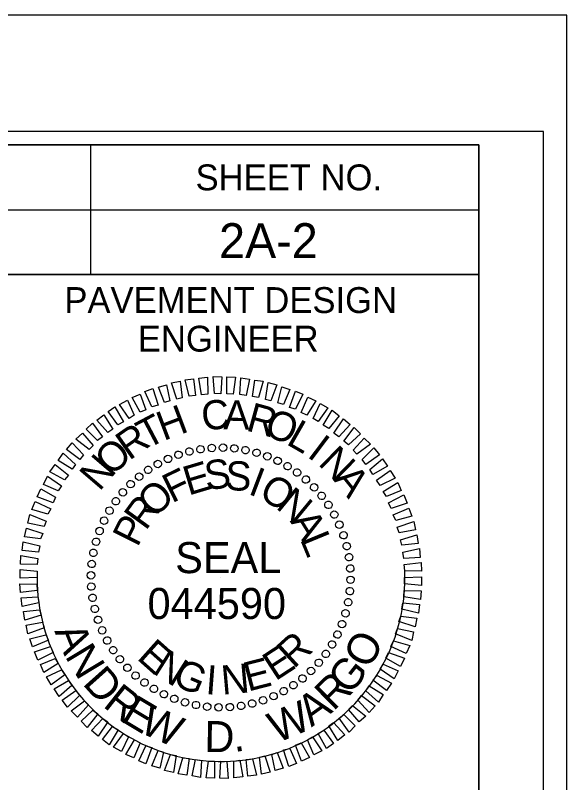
# Model space of a CAD drawing. Extents: x 3025871 to 3026431, y 707165 to 707825.
# Drawn here: x 3026258.64 to 3026274.62, y 707539.82 to 707562.05 of the extents above; entities that cross this region are included whole.
import ezdxf

# ---------------------------------------------------------------- set-up
doc = ezdxf.new("R2010")
doc.units = 0
for name, color, linetype in [('Old_Level_39', 7, 'Continuous'), ('Prop DSN Text', 7, 'Continuous'), ('Sheet Block Title CELL', 7, 'Continuous'), ('Sheet Cutting Line CELL', 7, 'Continuous'), ('Sheet Sticker Exception Certification CELL', 7, 'Continuous'), ('Typical Terminator CELL', 7, 'Continuous')]:
    doc.layers.add(name, color=color, linetype=linetype)

msp = doc.modelspace()

# ---------------------------------------------------------------- linework, layer by layer
at = {"layer": 'Old_Level_39'}
msp.add_lwpolyline([(3026273.948, 707558.686), (3026023.973, 707558.686), (3026023.973, 707400.421), (3026273.948, 707400.421)], close=True, dxfattribs=at)
at = {"layer": 'Prop DSN Text'}
msp.add_arc((3026264.604, 707545.767), 5.331, 180.0118, 2.0847, dxfattribs=at)
at = {"layer": 'Sheet Block Title CELL'}
for p, q in [((3026263.683, 707549.418), (3026263.683, 707549.418)), ((3026264.013, 707549.478), (3026264.013, 707549.478)), ((3026264.336, 707549.523), (3026264.336, 707549.523)), ((3026264.666, 707549.531), (3026264.666, 707549.531)), ((3026264.996, 707549.508), (3026264.996, 707549.508)), ((3026265.318, 707549.456), (3026265.318, 707549.456)), ((3026265.633, 707549.388), (3026265.633, 707549.388)), ((3026263.068, 707549.208), (3026263.068, 707549.208)), ((3026263.368, 707549.328), (3026263.368, 707549.328)), ((3026265.948, 707549.283), (3026265.948, 707549.283)), ((3026266.248, 707549.148), (3026266.248, 707549.148)), ((3026262.776, 707549.058), (3026262.776, 707549.058)), ((3026266.541, 707548.998), (3026266.541, 707548.998)), ((3026262.228, 707548.698), (3026262.228, 707548.698)), ((3026262.491, 707548.886), (3026262.491, 707548.886)), ((3026266.811, 707548.811), (3026266.811, 707548.811)), ((3026261.981, 707548.473), (3026261.981, 707548.473)), ((3026267.073, 707548.608), (3026267.073, 707548.608)), ((3026267.306, 707548.383), (3026267.306, 707548.383)), ((3026261.756, 707548.241), (3026261.756, 707548.241)), ((3026267.531, 707548.136), (3026267.531, 707548.136)), ((3026261.553, 707547.978), (3026261.553, 707547.978)), ((3026267.718, 707547.873), (3026267.718, 707547.873)), ((3026261.366, 707547.708), (3026261.366, 707547.708)), ((3026267.891, 707547.588), (3026267.891, 707547.588)), ((3026261.216, 707547.416), (3026261.216, 707547.416)), ((3026268.041, 707547.296), (3026268.041, 707547.296)), ((3026261.081, 707547.116), (3026261.081, 707547.116)), ((3026268.161, 707546.996), (3026268.161, 707546.996)), ((3026260.976, 707546.801), (3026260.976, 707546.801)), ((3026260.908, 707546.486), (3026260.908, 707546.486)), ((3026268.251, 707546.681), (3026268.251, 707546.681)), ((3026268.311, 707546.351), (3026268.311, 707546.351)), ((3026260.856, 707546.163), (3026260.856, 707546.163)), ((3026268.356, 707546.028), (3026268.356, 707546.028)), ((3026260.833, 707545.833), (3026260.833, 707545.833)), ((3026264.598, 707545.766), (3026264.598, 707545.766)), ((3026268.363, 707545.698), (3026268.363, 707545.698)), ((3026260.841, 707545.503), (3026260.841, 707545.503)), ((3026268.341, 707545.368), (3026268.341, 707545.368)), ((3026260.886, 707545.181), (3026260.886, 707545.181)), ((3026268.288, 707545.046), (3026268.288, 707545.046)), ((3026260.946, 707544.851), (3026260.946, 707544.851)), ((3026268.221, 707544.731), (3026268.221, 707544.731)), ((3026261.036, 707544.536), (3026261.036, 707544.536)), ((3026268.116, 707544.416), (3026268.116, 707544.416)), ((3026261.156, 707544.236), (3026261.156, 707544.236)), ((3026267.981, 707544.116), (3026267.981, 707544.116)), ((3026261.306, 707543.943), (3026261.306, 707543.943)), ((3026267.831, 707543.823), (3026267.831, 707543.823)), ((3026261.478, 707543.658), (3026261.478, 707543.658)), ((3026261.666, 707543.396), (3026261.666, 707543.396)), ((3026267.643, 707543.553), (3026267.643, 707543.553)), ((3026261.891, 707543.148), (3026261.891, 707543.148)), ((3026267.441, 707543.291), (3026267.441, 707543.291)), ((3026262.123, 707542.923), (3026262.123, 707542.923)), ((3026267.216, 707543.058), (3026267.216, 707543.058)), ((3026262.386, 707542.721), (3026262.386, 707542.721)), ((3026266.968, 707542.833), (3026266.968, 707542.833)), ((3026262.656, 707542.533), (3026262.656, 707542.533)), ((3026266.421, 707542.473), (3026266.421, 707542.473)), ((3026266.706, 707542.646), (3026266.706, 707542.646)), ((3026262.948, 707542.383), (3026262.948, 707542.383)), ((3026263.248, 707542.248), (3026263.248, 707542.248)), ((3026266.128, 707542.323), (3026266.128, 707542.323)), ((3026263.563, 707542.143), (3026263.563, 707542.143)), ((3026263.878, 707542.076), (3026263.878, 707542.076)), ((3026264.201, 707542.023), (3026264.201, 707542.023)), ((3026265.183, 707542.053), (3026265.183, 707542.053)), ((3026265.513, 707542.113), (3026265.513, 707542.113)), ((3026265.828, 707542.203), (3026265.828, 707542.203)), ((3026264.531, 707542.001), (3026264.531, 707542.001)), ((3026264.861, 707542.008), (3026264.861, 707542.008))]:
    msp.add_line(p, q, dxfattribs=at)
for points in [[(3026264.418, 707551.098), (3026264.381, 707551.586), (3026264.628, 707551.578), (3026264.598, 707551.091)], [(3026263.323, 707550.933), (3026263.166, 707551.406), (3026263.421, 707551.458), (3026263.481, 707550.971)], [(3026263.683, 707551.016), (3026263.563, 707551.496), (3026263.811, 707551.518), (3026263.863, 707551.038)], [(3026264.043, 707551.061), (3026263.961, 707551.541), (3026264.216, 707551.571), (3026264.223, 707551.083)], [(3026264.778, 707551.091), (3026264.778, 707551.578), (3026265.026, 707551.571), (3026264.958, 707551.083)], [(3026265.153, 707551.068), (3026265.183, 707551.556), (3026265.431, 707551.511), (3026265.333, 707551.038)], [(3026265.513, 707551.008), (3026265.581, 707551.488), (3026265.828, 707551.451), (3026265.693, 707550.986)], [(3026265.896, 707550.926), (3026265.971, 707551.413), (3026266.226, 707551.353), (3026266.053, 707550.888)], [(3026262.596, 707550.716), (3026262.401, 707551.151), (3026262.626, 707551.241), (3026262.783, 707550.761)], [(3026262.963, 707550.836), (3026262.791, 707551.286), (3026263.023, 707551.353), (3026263.121, 707550.888)], [(3026266.256, 707550.828), (3026266.368, 707551.293), (3026266.601, 707551.218), (3026266.413, 707550.776)], [(3026266.593, 707550.693), (3026266.766, 707551.166), (3026266.976, 707551.076), (3026266.766, 707550.641)], [(3026262.266, 707550.558), (3026262.026, 707550.978), (3026262.258, 707551.083), (3026262.431, 707550.626)], [(3026266.931, 707550.551), (3026267.118, 707550.993), (3026267.351, 707550.888), (3026267.096, 707550.468)], [(3026261.613, 707550.191), (3026261.336, 707550.573), (3026261.531, 707550.716), (3026261.778, 707550.281)], [(3026261.943, 707550.378), (3026261.666, 707550.783), (3026261.898, 707550.903), (3026262.086, 707550.468)], [(3026267.276, 707550.378), (3026267.478, 707550.806), (3026267.703, 707550.678), (3026267.418, 707550.288)], [(3026261.328, 707549.966), (3026261.006, 707550.326), (3026261.208, 707550.483), (3026261.471, 707550.063)], [(3026267.568, 707550.176), (3026267.831, 707550.611), (3026268.026, 707550.453), (3026267.733, 707550.086)], [(3026267.876, 707549.951), (3026268.153, 707550.363), (3026268.348, 707550.198), (3026268.018, 707549.846)], [(3026261.028, 707549.733), (3026260.698, 707550.063), (3026260.878, 707550.243), (3026261.171, 707549.838)], [(3026268.161, 707549.718), (3026268.468, 707550.108), (3026268.648, 707549.928), (3026268.303, 707549.606)], [(3026260.781, 707549.471), (3026260.398, 707549.778), (3026260.586, 707549.951), (3026260.901, 707549.591)], [(3026268.431, 707549.456), (3026268.753, 707549.808), (3026268.933, 707549.628), (3026268.543, 707549.336)], [(3026260.518, 707549.186), (3026260.128, 707549.478), (3026260.293, 707549.673), (3026260.623, 707549.321)], [(3026260.293, 707548.901), (3026259.888, 707549.156), (3026260.031, 707549.373), (3026260.391, 707549.043)], [(3026268.693, 707549.186), (3026269.038, 707549.523), (3026269.196, 707549.321), (3026268.798, 707549.036)], [(3026268.918, 707548.893), (3026269.286, 707549.208), (3026269.428, 707548.991), (3026269.008, 707548.751)], [(3026260.068, 707548.601), (3026259.648, 707548.826), (3026259.798, 707549.036), (3026260.188, 707548.736)], [(3026259.888, 707548.278), (3026259.461, 707548.466), (3026259.573, 707548.698), (3026259.978, 707548.421)], [(3026269.113, 707548.586), (3026269.511, 707548.871), (3026269.653, 707548.646), (3026269.218, 707548.436)], [(3026269.308, 707548.256), (3026269.728, 707548.518), (3026269.826, 707548.286), (3026269.398, 707548.113)], [(3026259.738, 707547.933), (3026259.273, 707548.106), (3026259.386, 707548.338), (3026259.813, 707548.098)], [(3026269.458, 707547.933), (3026269.901, 707548.158), (3026269.998, 707547.918), (3026269.533, 707547.768)], [(3026259.588, 707547.603), (3026259.123, 707547.738), (3026259.221, 707547.971), (3026259.671, 707547.761)], [(3026259.476, 707547.243), (3026259.011, 707547.341), (3026259.063, 707547.588), (3026259.536, 707547.401)], [(3026269.593, 707547.581), (3026270.051, 707547.776), (3026270.133, 707547.543), (3026269.668, 707547.423)], [(3026269.713, 707547.221), (3026270.193, 707547.393), (3026270.238, 707547.146), (3026269.766, 707547.063)], [(3026259.378, 707546.883), (3026258.913, 707546.943), (3026258.966, 707547.198), (3026259.438, 707547.041)], [(3026269.803, 707546.861), (3026270.276, 707547.003), (3026270.321, 707546.748), (3026269.848, 707546.703)], [(3026259.318, 707546.501), (3026258.838, 707546.546), (3026258.868, 707546.801), (3026259.356, 707546.681)], [(3026269.871, 707546.501), (3026270.358, 707546.606), (3026270.381, 707546.351), (3026269.901, 707546.321)], [(3026259.281, 707546.141), (3026258.793, 707546.156), (3026258.808, 707546.403), (3026259.296, 707546.321)], [(3026269.916, 707546.141), (3026270.403, 707546.201), (3026270.418, 707545.946), (3026269.931, 707545.961)], [(3026259.273, 707545.766), (3026258.786, 707545.743), (3026258.786, 707545.998), (3026259.273, 707545.946)], [(3026259.281, 707545.391), (3026258.793, 707545.331), (3026258.778, 707545.586), (3026259.266, 707545.571)], [(3026269.923, 707545.766), (3026270.411, 707545.788), (3026270.411, 707545.533), (3026269.923, 707545.586)], [(3026269.916, 707545.391), (3026270.403, 707545.376), (3026270.388, 707545.128), (3026269.901, 707545.211)], [(3026259.326, 707545.031), (3026258.838, 707544.926), (3026258.816, 707545.181), (3026259.296, 707545.211)], [(3026269.878, 707545.031), (3026270.358, 707544.986), (3026270.328, 707544.731), (3026269.841, 707544.851)], [(3026259.393, 707544.671), (3026258.921, 707544.528), (3026258.876, 707544.783), (3026259.348, 707544.828)], [(3026259.483, 707544.311), (3026259.003, 707544.138), (3026258.958, 707544.386), (3026259.431, 707544.468)], [(3026269.818, 707544.648), (3026270.283, 707544.588), (3026270.231, 707544.333), (3026269.758, 707544.491)], [(3026269.721, 707544.288), (3026270.186, 707544.191), (3026270.133, 707543.943), (3026269.661, 707544.131)], [(3026259.603, 707543.951), (3026259.146, 707543.756), (3026259.063, 707543.988), (3026259.528, 707544.108)], [(3026269.608, 707543.928), (3026270.073, 707543.793), (3026269.976, 707543.561), (3026269.526, 707543.771)], [(3026259.738, 707543.598), (3026259.296, 707543.373), (3026259.198, 707543.613), (3026259.663, 707543.763)], [(3026269.458, 707543.598), (3026269.923, 707543.426), (3026269.811, 707543.193), (3026269.383, 707543.433)], [(3026259.888, 707543.276), (3026259.468, 707543.013), (3026259.371, 707543.246), (3026259.798, 707543.418)], [(3026269.308, 707543.253), (3026269.736, 707543.066), (3026269.623, 707542.833), (3026269.218, 707543.111)], [(3026260.083, 707542.946), (3026259.686, 707542.661), (3026259.543, 707542.886), (3026259.978, 707543.096)], [(3026269.128, 707542.931), (3026269.548, 707542.706), (3026269.398, 707542.496), (3026269.008, 707542.796)], [(3026260.278, 707542.638), (3026259.911, 707542.323), (3026259.768, 707542.541), (3026260.188, 707542.781)], [(3026260.503, 707542.346), (3026260.158, 707542.008), (3026260.001, 707542.211), (3026260.398, 707542.496)], [(3026268.903, 707542.631), (3026269.308, 707542.376), (3026269.166, 707542.158), (3026268.806, 707542.488)], [(3026268.678, 707542.346), (3026269.068, 707542.053), (3026268.903, 707541.858), (3026268.573, 707542.211)], [(3026260.766, 707542.076), (3026260.443, 707541.723), (3026260.263, 707541.903), (3026260.653, 707542.196)], [(3026268.416, 707542.061), (3026268.798, 707541.753), (3026268.611, 707541.581), (3026268.296, 707541.941)], [(3026261.036, 707541.813), (3026260.728, 707541.423), (3026260.548, 707541.603), (3026260.893, 707541.926)], [(3026261.321, 707541.581), (3026261.043, 707541.168), (3026260.848, 707541.333), (3026261.178, 707541.686)], [(3026268.168, 707541.798), (3026268.498, 707541.468), (3026268.318, 707541.288), (3026268.026, 707541.693)], [(3026261.628, 707541.356), (3026261.366, 707540.921), (3026261.171, 707541.078), (3026261.463, 707541.446)], [(3026267.868, 707541.566), (3026268.191, 707541.206), (3026267.988, 707541.048), (3026267.726, 707541.468)], [(3026261.921, 707541.153), (3026261.718, 707540.726), (3026261.493, 707540.853), (3026261.778, 707541.243)], [(3026267.253, 707541.153), (3026267.531, 707540.748), (3026267.298, 707540.628), (3026267.111, 707541.063)], [(3026267.583, 707541.341), (3026267.861, 707540.958), (3026267.666, 707540.816), (3026267.418, 707541.251)], [(3026262.266, 707540.981), (3026262.078, 707540.538), (3026261.846, 707540.643), (3026262.101, 707541.063)], [(3026266.931, 707540.973), (3026267.171, 707540.553), (3026266.938, 707540.448), (3026266.766, 707540.906)], [(3026262.603, 707540.838), (3026262.431, 707540.366), (3026262.221, 707540.456), (3026262.431, 707540.891)], [(3026262.941, 707540.703), (3026262.828, 707540.238), (3026262.596, 707540.313), (3026262.783, 707540.756)], [(3026266.233, 707540.696), (3026266.406, 707540.246), (3026266.173, 707540.178), (3026266.076, 707540.643)], [(3026266.601, 707540.816), (3026266.796, 707540.381), (3026266.571, 707540.291), (3026266.413, 707540.771)], [(3026263.301, 707540.606), (3026263.226, 707540.118), (3026262.971, 707540.178), (3026263.143, 707540.643)], [(3026263.683, 707540.523), (3026263.616, 707540.043), (3026263.368, 707540.081), (3026263.503, 707540.546)], [(3026264.043, 707540.463), (3026264.013, 707539.976), (3026263.766, 707540.021), (3026263.863, 707540.493)], [(3026265.153, 707540.471), (3026265.236, 707539.991), (3026264.981, 707539.961), (3026264.973, 707540.448)], [(3026265.513, 707540.516), (3026265.633, 707540.036), (3026265.386, 707540.013), (3026265.333, 707540.493)], [(3026265.873, 707540.598), (3026266.031, 707540.126), (3026265.776, 707540.073), (3026265.716, 707540.561)], [(3026264.418, 707540.441), (3026264.418, 707539.953), (3026264.171, 707539.961), (3026264.238, 707540.448)], [(3026264.778, 707540.433), (3026264.816, 707539.946), (3026264.568, 707539.953), (3026264.598, 707540.441)]]:
    msp.add_lwpolyline(points, close=True, dxfattribs=at)
for centre, major_axis in [((3026264.01, 707549.481), (-0.017, 0.107)), ((3026264.336, 707549.518), (-0.008, 0.108)), ((3026264.664, 707549.527), (0.002, 0.108)), ((3026264.991, 707549.507), (0.011, 0.107)), ((3026263.373, 707549.323), (-0.035, 0.102)), ((3026263.688, 707549.416), (-0.026, 0.105)), ((3026265.316, 707549.458), (0.021, 0.106)), ((3026265.635, 707549.382), (0.03, 0.104)), ((3026265.946, 707549.278), (0.039, 0.101)), ((3026262.774, 707549.056), (-0.0524, 0.0945)), ((3026263.068, 707549.202), (-0.0439, 0.0987)), ((3026266.247, 707549.147), (0.0473, 0.0971)), ((3026262.495, 707548.884), (-0.0604, 0.0895)), ((3026266.536, 707548.99), (0.0556, 0.0926)), ((3026266.809, 707548.809), (0.0635, 0.0874)), ((3026262.231, 707548.689), (-0.068, 0.0839)), ((3026267.066, 707548.605), (0.0709, 0.0815)), ((3026261.985, 707548.472), (-0.075, 0.0777)), ((3026267.304, 707548.379), (0.0777, 0.075)), ((3026261.759, 707548.234), (-0.0815, 0.0709)), ((3026267.522, 707548.133), (0.0839, 0.068)), ((3026261.555, 707547.977), (-0.0874, 0.0635)), ((3026261.374, 707547.703), (-0.0926, 0.0556)), ((3026267.717, 707547.869), (0.0895, 0.0604)), ((3026267.889, 707547.589), (0.0945, 0.0524)), ((3026261.217, 707547.415), (-0.0971, 0.0473)), ((3026268.035, 707547.296), (0.0987, 0.0439)), ((3026261.086, 707547.114), (-0.101, 0.039)), ((3026260.982, 707546.803), (-0.104, 0.03)), ((3026268.155, 707546.99), (0.102, 0.035)), ((3026268.248, 707546.676), (0.105, 0.026)), ((3026260.905, 707546.483), (-0.106, 0.021)), ((3026268.314, 707546.354), (0.107, 0.017)), ((3026260.857, 707546.159), (-0.107, 0.011)), ((3026268.351, 707546.028), (0.108, 0.008)), ((3026260.837, 707545.831), (-0.108, 0.002)), ((3026268.36, 707545.7), (0.108, -0.002)), ((3026260.845, 707545.503), (-0.108, -0.008)), ((3026268.34, 707545.372), (0.107, -0.011)), ((3026260.883, 707545.177), (-0.107, -0.017)), ((3026268.291, 707545.048), (0.106, -0.021)), ((3026260.948, 707544.855), (-0.105, -0.026)), ((3026268.215, 707544.729), (0.104, -0.03)), ((3026261.041, 707544.541), (-0.102, -0.035)), ((3026268.11, 707544.417), (0.101, -0.039)), ((3026261.161, 707544.235), (-0.0987, -0.0439)), ((3026261.308, 707543.942), (-0.0945, -0.0524)), ((3026267.98, 707544.116), (0.0971, -0.0473)), ((3026267.823, 707543.828), (0.0926, -0.0556)), ((3026261.479, 707543.662), (-0.0895, -0.0604)), ((3026267.642, 707543.554), (0.0874, -0.0635)), ((3026261.675, 707543.398), (-0.0839, -0.068)), ((3026267.437, 707543.297), (0.0815, -0.0709)), ((3026261.892, 707543.152), (-0.0777, -0.075)), ((3026267.212, 707543.059), (0.075, -0.0777)), ((3026262.13, 707542.926), (-0.0709, -0.0815)), ((3026266.966, 707542.842), (0.068, -0.0839)), ((3026262.387, 707542.722), (-0.0635, -0.0874)), ((3026266.702, 707542.647), (0.0604, -0.0895)), ((3026262.661, 707542.541), (-0.0556, -0.0926)), ((3026262.949, 707542.384), (-0.0473, -0.0971)), ((3026266.422, 707542.475), (0.0524, -0.0945)), ((3026263.25, 707542.253), (-0.039, -0.101)), ((3026263.561, 707542.149), (-0.03, -0.104)), ((3026265.823, 707542.209), (0.035, -0.102)), ((3026266.128, 707542.329), (0.0439, -0.0987)), ((3026263.88, 707542.073), (-0.021, -0.106)), ((3026264.205, 707542.024), (-0.011, -0.107)), ((3026264.533, 707542.004), (-0.002, -0.108)), ((3026264.861, 707542.013), (0.008, -0.108)), ((3026265.187, 707542.05), (0.017, -0.107)), ((3026265.508, 707542.115), (0.026, -0.105))]:
    msp.add_ellipse(centre, major_axis=major_axis, ratio=0.999708, dxfattribs=at)
at = {"layer": 'Sheet Cutting Line CELL'}
for p, q in [((3026260.823, 707558.296), (3026260.823, 707554.546)), ((3026242.065, 707556.421), (3026272.073, 707556.421))]:
    msp.add_line(p, q, dxfattribs=at)
for points in [[(3026272.073, 707558.304), (3026047.073, 707558.304), (3026047.073, 707400.804), (3026272.073, 707400.804)], [(3026242.065, 707558.304), (3026272.073, 707558.304), (3026272.073, 707554.546), (3026242.065, 707554.546)], [(3026257.073, 707554.546), (3026272.073, 707554.546), (3026272.073, 707537.671), (3026257.073, 707537.671)]]:
    msp.add_lwpolyline(points, close=True, dxfattribs=at)
at = {"layer": 'Typical Terminator CELL'}
msp.add_lwpolyline([(3026274.623, 707562.054), (3026022.023, 707562.054), (3026022.023, 707397.054), (3026274.623, 707397.054)], close=True, dxfattribs=at)

# ---------------------------------------------------------------- texts
at = {"layer": 'Sheet Block Title CELL'}
for s, height, rotation, p in [('C', 0.846, 6.2199, (3026264.081, 707550.018)), ('H', 0.846, 20.6195, (3026262.941, 707549.718)), ('A', 0.846, 359.0203, (3026264.673, 707550.063)), ('R', 0.846, 344.6211, (3026265.303, 707550.033)), ('T', 0.846, 27.8198, (3026262.453, 707549.471)), ('O', 0.846, 337.4212, (3026265.806, 707549.921)), ('L', 0.846, 330.2209, (3026266.466, 707549.643)), ('R', 0.846, 35.0205, (3026261.943, 707549.141)), ('I', 0.846, 323.0201, (3026267.073, 707549.283)), ('O', 0.846, 42.2217, (3026261.426, 707548.676)), ('N', 0.846, 315.8189, (3026267.396, 707549.051)), ('N', 0.846, 49.4235, (3026261.081, 707548.241)), ('E', 0.846, 16.6111, (3026263.661, 707548.136)), ('S', 0.846, 7.2556, (3026264.178, 707548.293)), ('S', 0.846, 357.9004, (3026264.718, 707548.301)), ('F', 0.846, 25.967, (3026263.181, 707547.911)), ('I', 0.846, 339.1896, (3026265.363, 707548.196)), ('O', 0.846, 329.8335, (3026265.663, 707548.091)), ('A', 0.846, 308.6172, (3026267.838, 707548.608)), ('O', 0.846, 44.6812, (3026262.686, 707547.468)), ('N', 0.846, 320.4766, (3026266.166, 707547.791)), ('R', 0.846, 54.0397, (3026262.423, 707547.101)), ('P', 0.846, 63.3989, (3026262.183, 707546.621)), ('A', 0.846, 301.7603, (3026266.593, 707547.401)), ('L', 0.846, 292.4008, (3026266.886, 707546.883)), ('SEAL', 0.8997, 360, (3026263.278, 707545.893)), ('A', 0.9, 292.2016, (3026259.771, 707544.215)), ('R', 0.846, 42.4814, (3026266.713, 707543.103)), ('O', 0.9, 62.5158, (3026268.913, 707543.085)), ('N', 0.9, 301.0323, (3026260.066, 707543.492)), ('E', 0.846, 318.2769, (3026262.138, 707543.418)), ('E', 0.846, 33.1241, (3026266.181, 707542.751)), ('N', 0.846, 327.634, (3026262.588, 707543.013)), ('G', 0.846, 336.9902, (3026263.158, 707542.676)), ('E', 0.846, 14.4118, (3026265.386, 707542.458)), ('G', 0.9, 51.8017, (3026268.34, 707542.331)), ('D', 0.9, 311.7464, (3026260.568, 707542.688)), ('I', 0.846, 355.7012, (3026264.141, 707542.391)), ('N', 0.846, 5.0564, (3026264.643, 707542.368)), ('R', 0.9, 44.3296, (3026267.861, 707541.874)), ('R', 0.9, 321.6115, (3026261.155, 707542.042)), ('E', 0.9, 329.0836, (3026261.669, 707541.625)), ('A', 0.9, 35.4989, (3026267.225, 707541.42)), ('W', 0.9, 336.1852, (3026262.204, 707541.294)), ('W', 0.9, 22.9785, (3026266.22, 707540.955)), ('D', 0.9, 358.8948, (3026264.116, 707540.715)), ('.', 0.9, 8.7599, (3026264.989, 707540.706))]:
    msp.add_text(s, height=height, rotation=rotation, dxfattribs=at).set_placement(p)
msp.add_text('044590', height=0.8997, dxfattribs=at).set_placement((3026262.475, 707544.564))
at = {"layer": 'Sheet Cutting Line CELL'}
for s, height, p in [('SHEET NO.', 0.75, (3026263.868, 707556.984)), ('PAVEMENT DESIGN', 0.75001, (3026260.065, 707553.429)), ('ENGINEER', 0.75, (3026262.195, 707552.311))]:
    msp.add_text(s, height=height, rotation=360, dxfattribs=at).set_placement(p)
at = {"layer": 'Sheet Sticker Exception Certification CELL'}
msp.add_text('2A-2', height=1.0125, rotation=360, dxfattribs=at).set_placement((3026264.549, 707555.019))

doc.saveas('drawing.dxf')
